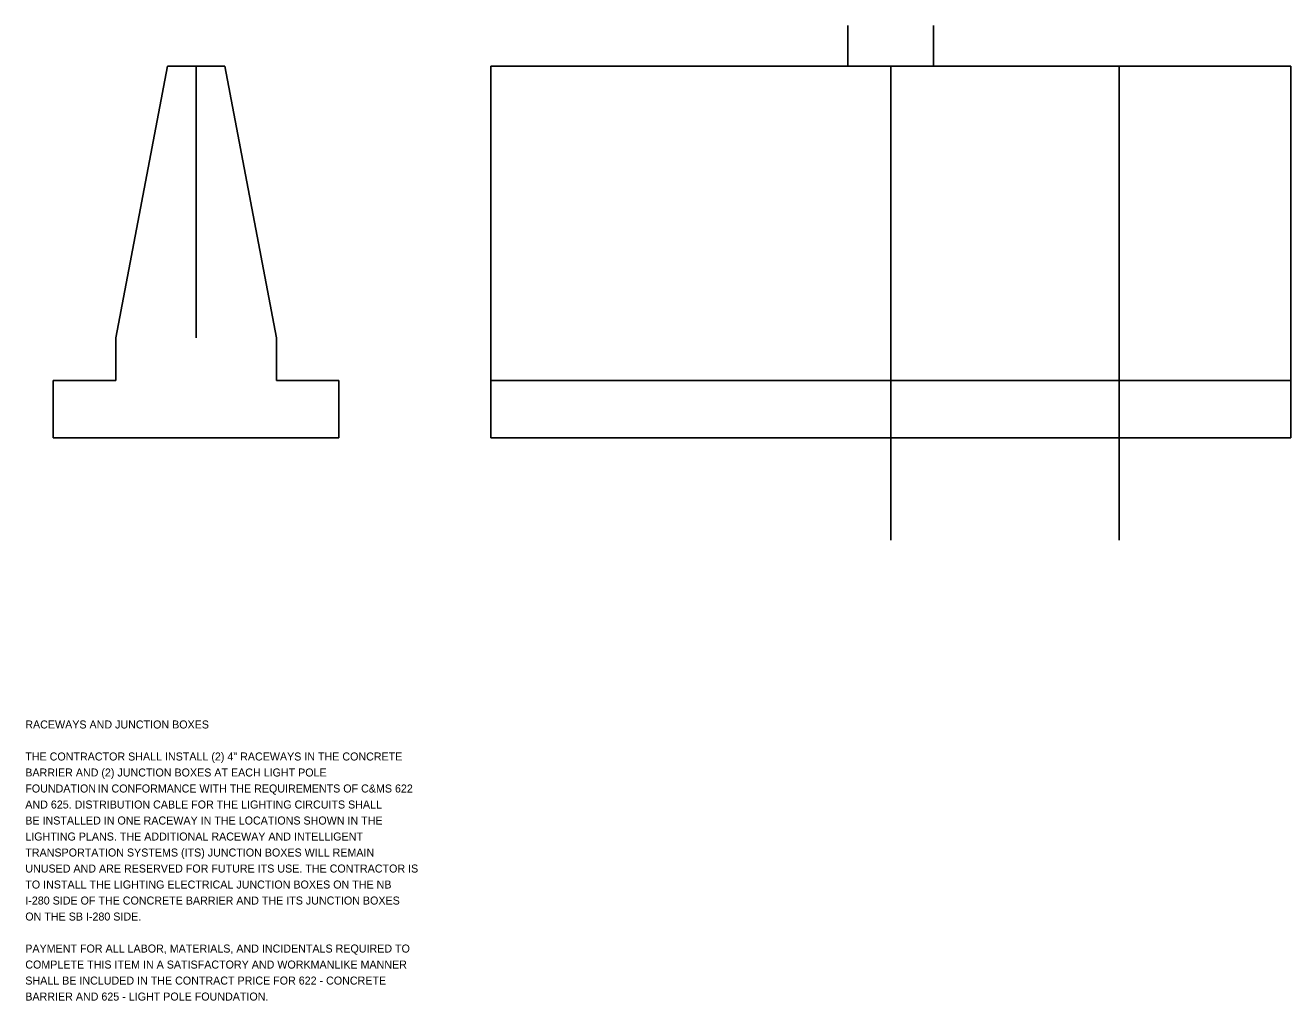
# Model space of a CAD drawing. Extents: x 0 to 59, y 0 to 22.
# Drawn here: x 36.82 to 58.96, y 1.4 to 18.46 of the extents above; entities that cross this region are included whole.
import ezdxf

# ---------------------------------------------------------------- set-up
doc = ezdxf.new("R2010")
doc.units = 0
doc.layers.add('SH_Text', color=7, linetype='Continuous')

msp = doc.modelspace()

# ---------------------------------------------------------------- linework, layer by layer
at = {"layer": 'SH_Text'}
for p, q in [((51.211, 17.746), (51.211, 18.461)), ((52.711, 17.746), (52.711, 18.461)), ((39.306, 17.746), (38.4, 12.996)), ((39.306, 17.746), (40.306, 17.746)), ((39.806, 17.746), (39.806, 12.996)), ((40.306, 17.746), (41.212, 12.996)), ((44.961, 17.746), (58.961, 17.746)), ((44.961, 11.246), (44.961, 17.746)), ((51.961, 17.746), (51.961, 9.455)), ((55.961, 17.746), (55.961, 9.455)), ((58.961, 11.246), (58.961, 17.746)), ((38.4, 12.246), (38.4, 12.996)), ((41.212, 12.246), (41.212, 12.996)), ((37.306, 12.246), (38.4, 12.246)), ((37.306, 12.246), (37.306, 11.246)), ((41.212, 12.246), (42.306, 12.246)), ((42.306, 12.246), (42.306, 11.246)), ((44.961, 12.246), (58.961, 12.246)), ((37.306, 11.246), (42.306, 11.246)), ((44.961, 11.246), (58.961, 11.246))]:
    msp.add_line(p, q, dxfattribs=at)

# ---------------------------------------------------------------- texts
for s, p in [('RACEWAYS AND JUNCTION BOXES', (36.817, 6.16)), ('THE CONTRACTOR SHALL INSTALL (2) 4" RACEWAYS IN THE CONCRETE ', (36.817, 5.6)), ('BARRIER AND (2) JUNCTION BOXES AT EACH LIGHT POLE', (36.817, 5.32)), ('FOUNDATION ', (36.817, 5.04)), ('IN CONFORMANCE WITH THE REQUIREMENTS OF C&MS 622 ', (38.086, 5.04)), ('AND 625. DISTRIBUTION CABLE FOR THE LIGHTING CIRCUITS SHALL ', (36.817, 4.76)), ('BE INSTALLED IN ONE RACEWAY IN THE LOCATIONS SHOWN IN THE ', (36.817, 4.48)), ('LIGHTING PLANS. THE ADDITIONAL RACEWAY AND INTELLIGENT', (36.817, 4.2)), ('TRANSPORTATION SYSTEMS (ITS) JUNCTION BOXES WILL REMAIN ', (36.817, 3.92)), ('UNUSED AND ARE RESERVED FOR FUTURE ITS USE. THE CONTRACTOR IS ', (36.817, 3.64)), ('TO INSTALL THE LIGHTING ELECTRICAL JUNCTION BOXES ON THE NB', (36.817, 3.36)), ('I-280 SIDE OF THE CONCRETE BARRIER AND THE ITS JUNCTION BOXES ', (36.817, 3.08)), ('ON THE SB I-280 SIDE. ', (36.817, 2.8)), ('PAYMENT FOR ALL LABOR, MATERIALS, AND INCIDENTALS REQUIRED TO ', (36.817, 2.24)), ('COMPLETE THIS ITEM IN A SATISFACTORY AND WORKMANLIKE MANNER ', (36.817, 1.96)), ('SHALL BE INCLUDED IN THE CONTRACT PRICE FOR 622 - CONCRETE ', (36.817, 1.68)), ('BARRIER AND 625 - LIGHT POLE FOUNDATION.', (36.817, 1.4))]:
    msp.add_text(s, height=0.14, dxfattribs=at).set_placement(p)

doc.saveas('drawing.dxf')
